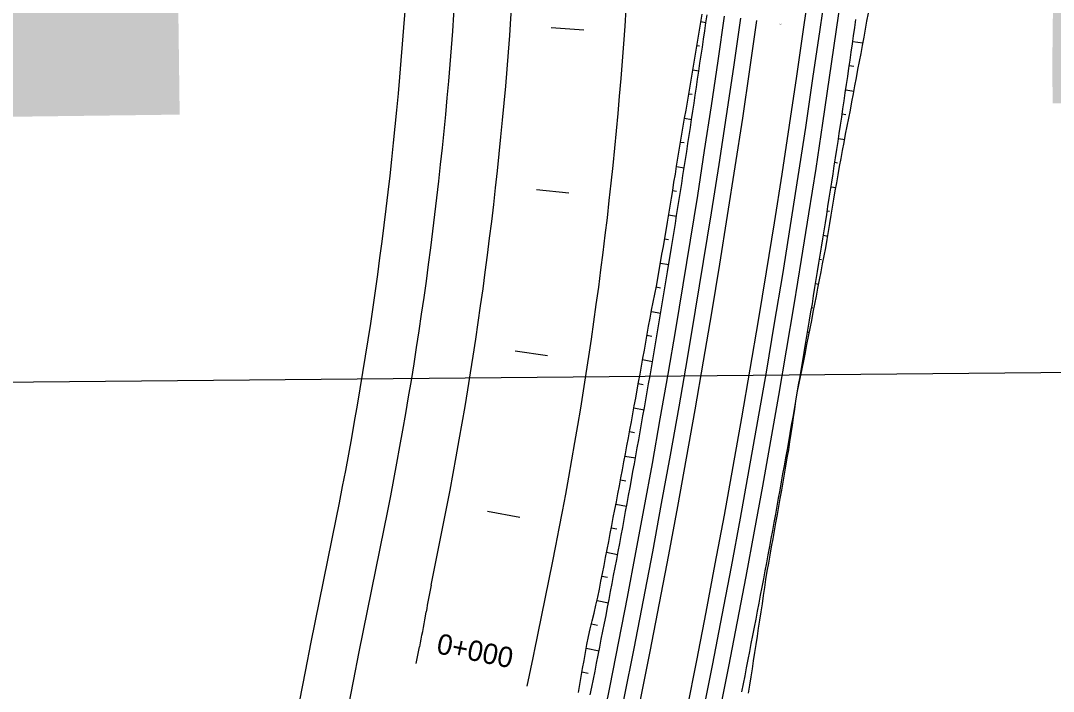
# Model space of a CAD drawing. Extents: x 6503541 to 6503743, y 5888004 to 5888145.
# Drawn here: x 6503702.276 to 6503703.793, y 5888114.929 to 5888115.915 of the extents above; entities that cross this region are included whole.
import ezdxf

# ---------------------------------------------------------------- set-up
doc = ezdxf.new("R2010")
doc.units = 0
doc.layers.add('12', color=7, linetype='Continuous')
doc.layers.add('tabela', color=7, linetype='Continuous')

msp = doc.modelspace()

# ---------------------------------------------------------------- linework, layer by layer
at = {"layer": '12'}
for p, q in [((6503703.4266, 5888115.9048), (6503705.2372, 5888128.6195)), ((6503703.4504, 5888115.9014), (6503705.2609, 5888128.6162)), ((6503703.4741, 5888115.898), (6503703.6039, 5888116.8095)), ((6503703.2754, 5888115.9133), (6503703.2827, 5888115.912)), ((6503703.2735, 5888115.8771), (6503703.2695, 5888115.8777)), ((6503703.4983, 5888115.884), (6503703.5133, 5888115.8819)), ((6503703.2636, 5888115.8422), (6503703.2723, 5888115.8408)), ((6503703.5, 5888115.8474), (6503703.4932, 5888115.8484)), ((6503703.488, 5888115.8128), (6503703.5001, 5888115.811)), ((6503703.2623, 5888115.8059), (6503703.2576, 5888115.8067)), ((6503703.2515, 5888115.7713), (6503703.2617, 5888115.7695)), ((6503703.488, 5888115.7764), (6503703.4827, 5888115.7772)), ((6503703.2508, 5888115.7349), (6503703.2453, 5888115.7358)), ((6503703.4774, 5888115.7416), (6503703.4865, 5888115.7402)), ((6503703.4759, 5888115.7054), (6503703.472, 5888115.706)), ((6503703.2396, 5888115.7002), (6503703.2508, 5888115.6984)), ((6503703.2395, 5888115.6638), (6503703.2338, 5888115.6647)), ((6503703.4665, 5888115.6704), (6503703.4735, 5888115.6693)), ((6503703.2279, 5888115.6292), (6503703.2396, 5888115.6273)), ((6503703.4642, 5888115.6343), (6503703.4609, 5888115.6348)), ((6503703.4553, 5888115.5993), (6503703.4617, 5888115.5982)), ((6503703.2279, 5888115.5927), (6503703.222, 5888115.5937)), ((6503703.216, 5888115.5582), (6503703.2281, 5888115.5561)), ((6503703.4524, 5888115.5633), (6503703.4496, 5888115.5637)), ((6503703.2159, 5888115.5216), (6503703.2096, 5888115.5228)), ((6503703.4438, 5888115.5282), (6503703.4484, 5888115.5274)), ((6503703.4398, 5888115.4924), (6503703.438, 5888115.4927)), ((6503703.2026, 5888115.4874), (6503703.2163, 5888115.4848)), ((6503703.2032, 5888115.4508), (6503703.1961, 5888115.4521)), ((6503703.4321, 5888115.4571), (6503703.4347, 5888115.4567)), ((6503703.1898, 5888115.4166), (6503703.2042, 5888115.414)), ((6503703.4269, 5888115.4215), (6503703.4261, 5888115.4216)), ((6503703.42, 5888115.3862), (6503703.4207, 5888115.386)), ((6503703.1907, 5888115.3798), (6503703.1834, 5888115.3812)), ((6503703.1769, 5888115.3458), (6503703.1919, 5888115.343)), ((6503703.178, 5888115.3089), (6503703.1704, 5888115.3104)), ((6503703.1638, 5888115.275), (6503703.1792, 5888115.2721)), ((6503703.165, 5888115.2381), (6503703.1572, 5888115.2396)), ((6503703.1505, 5888115.2042), (6503703.1663, 5888115.2012)), ((6503702.703, 5888115.0015), (6503702.7396, 5888115.1823)), ((6503702.7735, 5888114.9872), (6503702.8102, 5888115.168)), ((6503703.1517, 5888115.1673), (6503703.1437, 5888115.1689)), ((6503702.8791, 5888115.0853), (6503702.8925, 5888115.1513)), ((6503703.1369, 5888115.1335), (6503703.1531, 5888115.1303)), ((6503703.0309, 5888114.9885), (6503703.0572, 5888115.1179)), ((6503703.1381, 5888115.0965), (6503703.1299, 5888115.0982)), ((6503703.1228, 5888115.0629), (6503703.1395, 5888115.0592)), ((6503702.8708, 5888115.0399), (6503702.8719, 5888115.046)), ((6503703.1236, 5888115.0258), (6503703.1145, 5888115.0279)), ((6503702.8572, 5888114.9702), (6503702.8623, 5888114.9948)), ((6503703.1068, 5888114.9927), (6503703.1258, 5888114.989)), ((6503703.02, 5888114.9367), (6503703.0288, 5888114.9785)), ((6503703.1098, 5888114.9556), (6503703.1007, 5888114.9572))]:
    msp.add_line(p, q, dxfattribs=at)
for points in [[(6503703.0954, 5888114.9274), (6503703.0975, 5888114.9392), (6503703.0995, 5888114.9509), (6503703.1016, 5888114.9627), (6503703.1037, 5888114.9744), (6503703.1057, 5888114.9861), (6503703.1077, 5888114.9979), (6503703.1101, 5888115.0096), (6503703.1129, 5888115.0212), (6503703.1157, 5888115.0327), (6503703.1184, 5888115.0443), (6503703.1212, 5888115.0559), (6503703.1239, 5888115.0676), (6503703.1262, 5888115.0793), (6503703.1285, 5888115.0909), (6503703.1308, 5888115.1026), (6503703.1331, 5888115.1143), (6503703.1354, 5888115.126), (6503703.1377, 5888115.1377), (6503703.14, 5888115.1494), (6503703.1422, 5888115.1611), (6503703.1445, 5888115.1728), (6503703.1467, 5888115.1845), (6503703.149, 5888115.1962), (6503703.1512, 5888115.2079), (6503703.1534, 5888115.2196), (6503703.1556, 5888115.2313), (6503703.1579, 5888115.2431), (6503703.1601, 5888115.2548), (6503703.1623, 5888115.2665), (6503703.1644, 5888115.2782), (6503703.1666, 5888115.2899), (6503703.1688, 5888115.3016), (6503703.171, 5888115.3133), (6503703.1732, 5888115.3251), (6503703.1753, 5888115.3368), (6503703.1775, 5888115.3485), (6503703.1796, 5888115.3602), (6503703.1817, 5888115.372), (6503703.1839, 5888115.3837), (6503703.186, 5888115.3954), (6503703.1881, 5888115.4071), (6503703.1902, 5888115.4189), (6503703.1923, 5888115.4306), (6503703.1944, 5888115.4423), (6503703.1964, 5888115.4541), (6503703.1985, 5888115.4658), (6503703.2007, 5888115.4775), (6503703.203, 5888115.4892), (6503703.2053, 5888115.5009), (6503703.2076, 5888115.5126), (6503703.2099, 5888115.5243), (6503703.2121, 5888115.536), (6503703.2142, 5888115.5478), (6503703.2162, 5888115.5595), (6503703.2182, 5888115.5713), (6503703.2202, 5888115.583), (6503703.2222, 5888115.5948), (6503703.2242, 5888115.6065), (6503703.2261, 5888115.6183), (6503703.2281, 5888115.6301), (6503703.23, 5888115.6418), (6503703.232, 5888115.6536), (6503703.2339, 5888115.6653), (6503703.2358, 5888115.6771), (6503703.2378, 5888115.6889), (6503703.2397, 5888115.7006), (6503703.2416, 5888115.7124), (6503703.2435, 5888115.7242), (6503703.2453, 5888115.7359), (6503703.2474, 5888115.7477), (6503703.2494, 5888115.7594), (6503703.2515, 5888115.7712), (6503703.2535, 5888115.7829), (6503703.2555, 5888115.7947), (6503703.2575, 5888115.8064), (6503703.2595, 5888115.8182), (6503703.2615, 5888115.8299), (6503703.2635, 5888115.8417), (6503703.2655, 5888115.8535), (6503703.2675, 5888115.8652), (6503703.2694, 5888115.877), (6503703.2714, 5888115.8887), (6503703.2733, 5888115.9005), (6503703.2753, 5888115.9123), (6503703.2772, 5888115.924)], [(6503703.1129, 5888114.9239), (6503703.1152, 5888114.9356), (6503703.1175, 5888114.9473), (6503703.1199, 5888114.959), (6503703.1222, 5888114.9707), (6503703.1245, 5888114.9824), (6503703.1268, 5888114.9941), (6503703.1291, 5888115.0058), (6503703.1314, 5888115.0175), (6503703.1337, 5888115.0292), (6503703.136, 5888115.0409), (6503703.1382, 5888115.0527), (6503703.1405, 5888115.0644), (6503703.1427, 5888115.0761), (6503703.145, 5888115.0878), (6503703.1472, 5888115.0995), (6503703.1495, 5888115.1112), (6503703.1517, 5888115.1229), (6503703.1539, 5888115.1347), (6503703.1561, 5888115.1464), (6503703.1583, 5888115.1581), (6503703.1605, 5888115.1698), (6503703.1627, 5888115.1816), (6503703.1648, 5888115.1933), (6503703.167, 5888115.205), (6503703.1691, 5888115.2168), (6503703.1713, 5888115.2285), (6503703.1734, 5888115.2402), (6503703.1756, 5888115.252), (6503703.1777, 5888115.2637), (6503703.1798, 5888115.2754), (6503703.1819, 5888115.2872), (6503703.184, 5888115.2989), (6503703.1861, 5888115.3107), (6503703.1882, 5888115.3224), (6503703.1903, 5888115.3341), (6503703.1924, 5888115.3459), (6503703.1944, 5888115.3576), (6503703.1965, 5888115.3694), (6503703.1985, 5888115.3811), (6503703.2006, 5888115.3929), (6503703.2026, 5888115.4046), (6503703.2046, 5888115.4164), (6503703.2066, 5888115.4281), (6503703.2087, 5888115.4399), (6503703.2107, 5888115.4517), (6503703.2127, 5888115.4634), (6503703.2146, 5888115.4752), (6503703.2166, 5888115.4869), (6503703.2186, 5888115.4987), (6503703.2205, 5888115.5105), (6503703.2225, 5888115.5222), (6503703.2244, 5888115.534), (6503703.2264, 5888115.5458), (6503703.2283, 5888115.5576), (6503703.2302, 5888115.5693), (6503703.2322, 5888115.5811), (6503703.2341, 5888115.5929), (6503703.236, 5888115.6046), (6503703.2378, 5888115.6164), (6503703.2397, 5888115.6282), (6503703.2416, 5888115.64), (6503703.2435, 5888115.6518), (6503703.2453, 5888115.6635), (6503703.2472, 5888115.6753), (6503703.249, 5888115.6871), (6503703.2509, 5888115.6989), (6503703.2527, 5888115.7107), (6503703.2545, 5888115.7225), (6503703.2563, 5888115.7343), (6503703.2581, 5888115.746), (6503703.2599, 5888115.7578), (6503703.2617, 5888115.7696), (6503703.2635, 5888115.7814), (6503703.2653, 5888115.7932), (6503703.267, 5888115.805), (6503703.2688, 5888115.8168), (6503703.2705, 5888115.8286), (6503703.2723, 5888115.8404), (6503703.274, 5888115.8522), (6503703.2757, 5888115.864), (6503703.2775, 5888115.8758), (6503703.2792, 5888115.8876), (6503703.2809, 5888115.8994), (6503703.2826, 5888115.9112), (6503703.2843, 5888115.923)], [(6503703.3355, 5888114.9285), (6503703.3378, 5888114.9403), (6503703.3402, 5888114.9522), (6503703.3425, 5888114.964), (6503703.3448, 5888114.9758), (6503703.3471, 5888114.9877), (6503703.3494, 5888114.9996), (6503703.3517, 5888115.0114), (6503703.354, 5888115.0233), (6503703.3563, 5888115.0351), (6503703.3586, 5888115.047), (6503703.3608, 5888115.0588), (6503703.3631, 5888115.0707), (6503703.3653, 5888115.0825), (6503703.3676, 5888115.0944), (6503703.3698, 5888115.1063), (6503703.372, 5888115.1181), (6503703.3742, 5888115.13), (6503703.3764, 5888115.1419), (6503703.3786, 5888115.1537), (6503703.3808, 5888115.1656), (6503703.383, 5888115.1775), (6503703.3852, 5888115.1894), (6503703.3874, 5888115.2012), (6503703.3895, 5888115.2131), (6503703.3917, 5888115.225), (6503703.3938, 5888115.2369), (6503703.3959, 5888115.2488), (6503703.3981, 5888115.2606), (6503703.4002, 5888115.2725), (6503703.4023, 5888115.2844), (6503703.4044, 5888115.2963), (6503703.4065, 5888115.3082), (6503703.4086, 5888115.3201), (6503703.4107, 5888115.332), (6503703.4128, 5888115.3439), (6503703.4148, 5888115.3558), (6503703.4169, 5888115.3677), (6503703.4189, 5888115.3796), (6503703.421, 5888115.3915), (6503703.423, 5888115.4034), (6503703.425, 5888115.4153), (6503703.427, 5888115.4272), (6503703.429, 5888115.4391), (6503703.4311, 5888115.451), (6503703.433, 5888115.4629), (6503703.435, 5888115.4748), (6503703.437, 5888115.4867), (6503703.439, 5888115.4986), (6503703.4409, 5888115.5105), (6503703.4429, 5888115.5224), (6503703.4448, 5888115.5343), (6503703.4468, 5888115.5463), (6503703.4487, 5888115.5582), (6503703.4506, 5888115.5701), (6503703.4525, 5888115.582), (6503703.4544, 5888115.5939), (6503703.4563, 5888115.6059), (6503703.4582, 5888115.6178), (6503703.4601, 5888115.6297), (6503703.462, 5888115.6416), (6503703.4639, 5888115.6536), (6503703.4657, 5888115.6655), (6503703.4676, 5888115.6774), (6503703.4694, 5888115.6894), (6503703.4712, 5888115.7013), (6503703.4731, 5888115.7132), (6503703.4749, 5888115.7252), (6503703.4767, 5888115.7371), (6503703.4785, 5888115.749), (6503703.4803, 5888115.761), (6503703.4821, 5888115.7729), (6503703.4839, 5888115.7848), (6503703.4856, 5888115.7968), (6503703.4874, 5888115.8087), (6503703.4892, 5888115.8207), (6503703.4909, 5888115.8326), (6503703.4926, 5888115.8446), (6503703.4944, 5888115.8565), (6503703.4961, 5888115.8685), (6503703.4978, 5888115.8804), (6503703.4995, 5888115.8924), (6503703.5012, 5888115.9043), (6503703.5029, 5888115.9161)], [(6503703.4169, 5888115.3676), (6503703.4193, 5888115.3795), (6503703.4217, 5888115.3913), (6503703.4241, 5888115.4032), (6503703.4264, 5888115.415), (6503703.4288, 5888115.4269), (6503703.4311, 5888115.4387), (6503703.4335, 5888115.4506), (6503703.4358, 5888115.4624), (6503703.4381, 5888115.4743), (6503703.4404, 5888115.4861), (6503703.4427, 5888115.498), (6503703.445, 5888115.5098), (6503703.4473, 5888115.5217), (6503703.4496, 5888115.5336), (6503703.4518, 5888115.5454), (6503703.4541, 5888115.5573), (6503703.4564, 5888115.5692), (6503703.4586, 5888115.581), (6503703.4608, 5888115.5929), (6503703.4627, 5888115.6048), (6503703.4647, 5888115.6168), (6503703.4667, 5888115.6287), (6503703.4686, 5888115.6406), (6503703.4706, 5888115.6525), (6503703.4727, 5888115.6644), (6503703.4748, 5888115.6763), (6503703.4769, 5888115.6882), (6503703.479, 5888115.7001), (6503703.4811, 5888115.712), (6503703.4833, 5888115.7239), (6503703.4856, 5888115.7357), (6503703.4879, 5888115.7476), (6503703.4902, 5888115.7595), (6503703.4925, 5888115.7713), (6503703.4948, 5888115.7832), (6503703.4971, 5888115.7951), (6503703.4993, 5888115.807), (6503703.5016, 5888115.8189), (6503703.5038, 5888115.8307), (6503703.506, 5888115.8426), (6503703.5083, 5888115.8545), (6503703.5105, 5888115.8664), (6503703.5127, 5888115.8783), (6503703.5149, 5888115.8902), (6503703.517, 5888115.902), (6503703.5192, 5888115.9138), (6503703.5214, 5888115.9256)], [(6503703.1034, 5888115.9008), (6503703.0555, 5888115.9042)], [(6503703.0815, 5888115.6609), (6503703.0338, 5888115.6662)], [(6503703.0501, 5888115.422), (6503703.0027, 5888115.4292)], [(6503703.3454, 5888114.9265), (6503703.3472, 5888114.9385), (6503703.3491, 5888114.9504), (6503703.351, 5888114.9623), (6503703.3528, 5888114.9743), (6503703.3547, 5888114.9862), (6503703.3565, 5888114.9982), (6503703.3583, 5888115.0101), (6503703.3601, 5888115.0221), (6503703.362, 5888115.034), (6503703.3638, 5888115.046), (6503703.3656, 5888115.0579), (6503703.3674, 5888115.0699), (6503703.3691, 5888115.0818), (6503703.3709, 5888115.0938), (6503703.3728, 5888115.1057), (6503703.3749, 5888115.1176), (6503703.3771, 5888115.1295), (6503703.3792, 5888115.1414), (6503703.3814, 5888115.1532), (6503703.3835, 5888115.1651), (6503703.3856, 5888115.177), (6503703.3877, 5888115.1889), (6503703.3898, 5888115.2008), (6503703.3919, 5888115.2127), (6503703.394, 5888115.2246), (6503703.3961, 5888115.2365), (6503703.3981, 5888115.2484), (6503703.4002, 5888115.2603), (6503703.4022, 5888115.2722), (6503703.4043, 5888115.2841), (6503703.4061, 5888115.296), (6503703.4079, 5888115.3079), (6503703.4097, 5888115.3199), (6503703.4115, 5888115.3318), (6503703.4133, 5888115.3438), (6503703.415, 5888115.3557), (6503703.4169, 5888115.3676)], [(6503703.0092, 5888115.1845), (6503702.9621, 5888115.1936)]]:
    msp.add_lwpolyline(points, dxfattribs=at)
for centre, radius, start, end in [((6503697.0946, 5888116.3273), 5.76, 348.53445, 356.27387), ((6503697.0946, 5888116.3273), 5.832, 348.53445, 356.27387), ((6503697.0946, 5888116.3273), 5.916, 348.53445, 356.27387), ((6503697.0946, 5888116.3273), 6.084, 348.53445, 356.27387), ((6503685.5719, 5888118.4473), 17.9412, 322.48762, 351.89568), ((6503685.5719, 5888118.4473), 17.9172, 324.73339, 351.89568), ((6503685.5719, 5888118.4473), 17.9652, 322.48762, 351.89568), ((6503685.5719, 5888118.4473), 18.0348, 322.48762, 351.89568), ((6503685.5719, 5888118.4473), 18.0588, 322.48762, 351.89568), ((6503685.5719, 5888118.4473), 18.0828, 324.58652, 351.89568), ((6503704.0552, 5888114.8468), 1.2, 168.5345, 170.4434), ((6503701.6875, 5888115.2391), 1.2, 348.2519, 350.4434), ((6503688.7485, 5888117.6934), 14.2117, 337.85643, 349.08053), ((6503688.7534, 5888117.692), 14.2786, 337.85225, 349.08068), ((6503701.8549, 5888115.2271), 1.2, 348.0426, 348.5345)]:
    msp.add_arc(centre, radius, start, end, dxfattribs=at)
at = {"layer": 'tabela'}
msp.add_line((6503707.1383, 5888115.4285), (6503699.9029, 5888115.3609), dxfattribs=at)
msp.add_line((6503707.1383, 5888115.4285), (6503699.9029, 5888115.3609), dxfattribs=at)

# ---------------------------------------------------------------- texts
at = {"layer": '12'}
for s, height, rotation, p in [('17', 4.22297, 0.7393, (6503699.6452, 5888115.7396)), ('C', 0.0024, 81.8957, (6503703.3932, 5888115.9083)), ('0+000', 0.03, 348.5345, (6503702.8856, 5888114.9854))]:
    msp.add_text(s, height=height, rotation=rotation, dxfattribs=at).set_placement(p)

doc.saveas('drawing.dxf')
